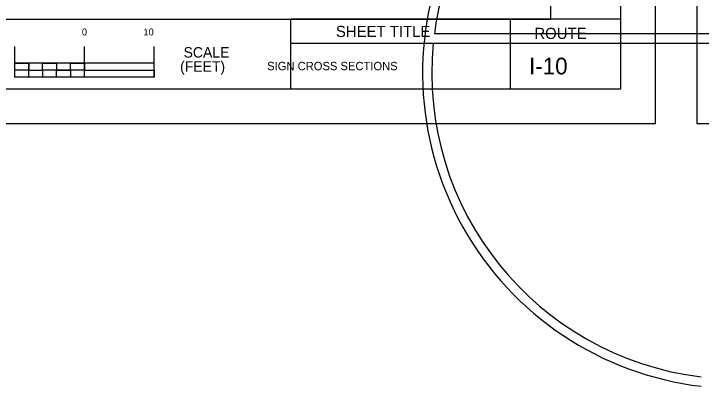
# Model space of a CAD drawing. Extents: x 2193008 to 2198143, y 1236112 to 1237864.
# Drawn here: x 2195451.7 to 2195550.3, y 1237080.3 to 1237133.8 of the extents above; entities that cross this region are included whole.
import ezdxf

# ---------------------------------------------------------------- set-up
doc = ezdxf.new("R2010")
doc.units = 0
for name, color, linetype in [('ANNO-SHT', 7, 'Continuous'), ('ANNO-SYMB', 7, 'Continuous'), ('ANNO-TXT', 7, 'Continuous'), ('GSOUTLINE', 7, 'Continuous'), ('Level 6', 7, 'Continuous'), ('M-ROADS', 7, 'Continuous'), ('SHT-BNDRY', 7, 'Continuous')]:
    doc.layers.add(name, color=color, linetype=linetype)

msp = doc.modelspace()

# ---------------------------------------------------------------- linework, layer by layer
msp.add_lwpolyline([(2195228.783, 1237133.046), (2195528.783, 1237133.046), (2195528.783, 1237323.046), (2195228.783, 1237323.046)], close=True)
at = {"layer": 'ANNO-SYMB'}
for p, q in [((2195451.851, 1237124.7), (2195451.851, 1237129.1)), ((2195461.851, 1237124.7), (2195461.851, 1237129.1)), ((2195461.851, 1237124.7), (2195461.851, 1237129.1)), ((2195461.851, 1237124.7), (2195461.851, 1237129.1)), ((2195471.851, 1237124.7), (2195471.851, 1237129.1)), ((2195471.851, 1237126.7), (2195451.851, 1237126.7)), ((2195453.851, 1237125.7), (2195453.851, 1237126.7)), ((2195453.851, 1237125.7), (2195453.851, 1237126.7)), ((2195461.851, 1237125.7), (2195461.851, 1237126.7)), ((2195461.851, 1237125.7), (2195461.851, 1237126.7)), ((2195461.851, 1237125.7), (2195461.851, 1237126.7)), ((2195461.851, 1237125.7), (2195457.851, 1237125.7)), ((2195471.851, 1237124.7), (2195471.851, 1237125.7)), ((2195471.851, 1237124.7), (2195471.851, 1237125.7)), ((2195471.851, 1237124.7), (2195471.851, 1237125.7)), ((2195471.851, 1237124.7), (2195451.851, 1237124.7))]:
    msp.add_line(p, q, dxfattribs=at)
for points in [[(2195451.851, 1237126.7), (2195453.851, 1237126.7), (2195453.851, 1237125.7), (2195451.851, 1237125.7)], [(2195455.851, 1237126.7), (2195457.851, 1237126.7), (2195457.851, 1237125.7), (2195455.851, 1237125.7)], [(2195459.851, 1237126.7), (2195461.851, 1237126.7), (2195461.851, 1237125.7), (2195459.851, 1237125.7)], [(2195453.851, 1237125.7), (2195455.851, 1237125.7), (2195455.851, 1237124.7), (2195453.851, 1237124.7)], [(2195457.851, 1237125.7), (2195459.851, 1237125.7), (2195459.851, 1237124.7), (2195457.851, 1237124.7)], [(2195461.851, 1237125.7), (2195471.851, 1237125.7), (2195471.851, 1237124.7), (2195461.851, 1237124.7)]]:
    msp.add_lwpolyline(points, close=True, dxfattribs=at)
at = {"layer": 'ANNO-TXT'}
for p, q in [((2195491.446, 1237129.575), (2195522.974, 1237129.575)), ((2195522.974, 1237129.575), (2195538.786, 1237129.575))]:
    msp.add_line(p, q, dxfattribs=at)
at = {"layer": 'GSOUTLINE'}
for points in [[(2195588.638, 1237130.947), (2195512.056, 1237130.947)], [(2195511.905, 1237129.614), (2195588.79, 1237129.614)]]:
    msp.add_lwpolyline(points, dxfattribs=at)
for major_axis, start_param, end_param in [((45.319, 0), 2.709569, 4.594469), ((43.986, 0), 2.735396, 3.01287), ((43.986, 0), 3.043371, 4.590878)]:
    msp.add_ellipse((2195555.679, 1237125.301), major_axis=major_axis, ratio=0.999829, start_param=start_param, end_param=end_param, dxfattribs=at)
at = {"layer": 'Level 6'}
msp.add_line((2195538.786, 1237133.046), (2195491.446, 1237133.046), dxfattribs=at)
at = {"layer": 'M-ROADS'}
for points in [[(2195203.786, 1237118.036), (2195543.786, 1237118.036), (2195543.786, 1237338.036), (2195203.786, 1237338.036)], [(2195549.71, 1237118.036), (2195889.71, 1237118.036), (2195889.71, 1237338.036), (2195549.71, 1237338.036)]]:
    msp.add_lwpolyline(points, close=True, dxfattribs=at)
at = {"layer": 'SHT-BNDRY'}
for p, q in [((2195491.446, 1237123.036), (2195491.446, 1237133.046)), ((2195522.974, 1237123.036), (2195522.974, 1237133.046))]:
    msp.add_line(p, q, dxfattribs=at)
msp.add_lwpolyline([(2195216.286, 1237123.036), (2195538.786, 1237123.036), (2195538.786, 1237333.036), (2195216.286, 1237333.036)], close=True, dxfattribs=at)

# ---------------------------------------------------------------- texts
at = {"layer": 'ANNO-SHT'}
for s, height, p in [('          SIGN CROSS SECTIONS          ', 1.2, (2195483.61, 1237125.706)), (' I-10 ', 2.4, (2195524.75, 1237125.106))]:
    msp.add_text(s, height=height, rotation=360, dxfattribs=at).set_placement(p)
at = {"layer": 'ANNO-SYMB'}
for s, height, p in [('0', 1, (2195461.477, 1237130.7)), ('0', 1, (2195461.477, 1237130.7)), ('0', 1, (2195461.477, 1237130.7)), (' 10', 0.9991, (2195469.932, 1237130.7)), ('SCALE', 1.4994, (2195476.076, 1237127.522)), ('(FEET)', 1.4994, (2195475.576, 1237125.493))]:
    msp.add_text(s, height=height, rotation=0.0572, dxfattribs=at).set_placement(p)
at = {"layer": 'ANNO-TXT'}
for s, p in [('SHEET TITLE', (2195497.932, 1237130.478)), ('ROUTE', (2195526.405, 1237130.197))]:
    msp.add_text(s, height=1.6, dxfattribs=at).set_placement(p)

doc.saveas('drawing.dxf')
